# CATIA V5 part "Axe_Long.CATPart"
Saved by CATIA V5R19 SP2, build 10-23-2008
Part number: Axe_Long_2
Bounding box of the stored display mesh (mm): x 0 to 5, y -1 to 1, z -1 to 1
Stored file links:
  G:\EU_thinkMotion\CFAO_2010\MMS_groupe3\MMS_groupe3\A reprendre\lletoffe\lletoffe_Thinkmotion_CFAO\Modèle Catia\Axe_Long.CATPart
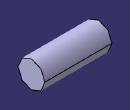
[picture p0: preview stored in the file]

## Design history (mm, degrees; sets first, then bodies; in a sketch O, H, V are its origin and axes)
Parameters
  Epaisseur = 1 mm
Set1
  Point1: (0, 0, 0)
  Point2: (1, 0, 0)
  Line1: type PtPt, FirstPoint Point1, SecondPoint Point2, Start 10, End 10
  Plane1: type Offset, RefPlane yz-plane, Offset 5 {= 5*Epaisseur}
  Sketch1 on yz-plane, origin (0, 0, 0), H (0, 1, 0), V (0, 0, 1)
    circle A1 centre (0, 0) radius 1
    reference projected point E1 (0, 0) from Line1
    radius A1 = 1
    concentricity: E1 A1
Body1 (main body)
  Pad1: profile Sketch1, direction (1, 0, 0), up to Plane1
